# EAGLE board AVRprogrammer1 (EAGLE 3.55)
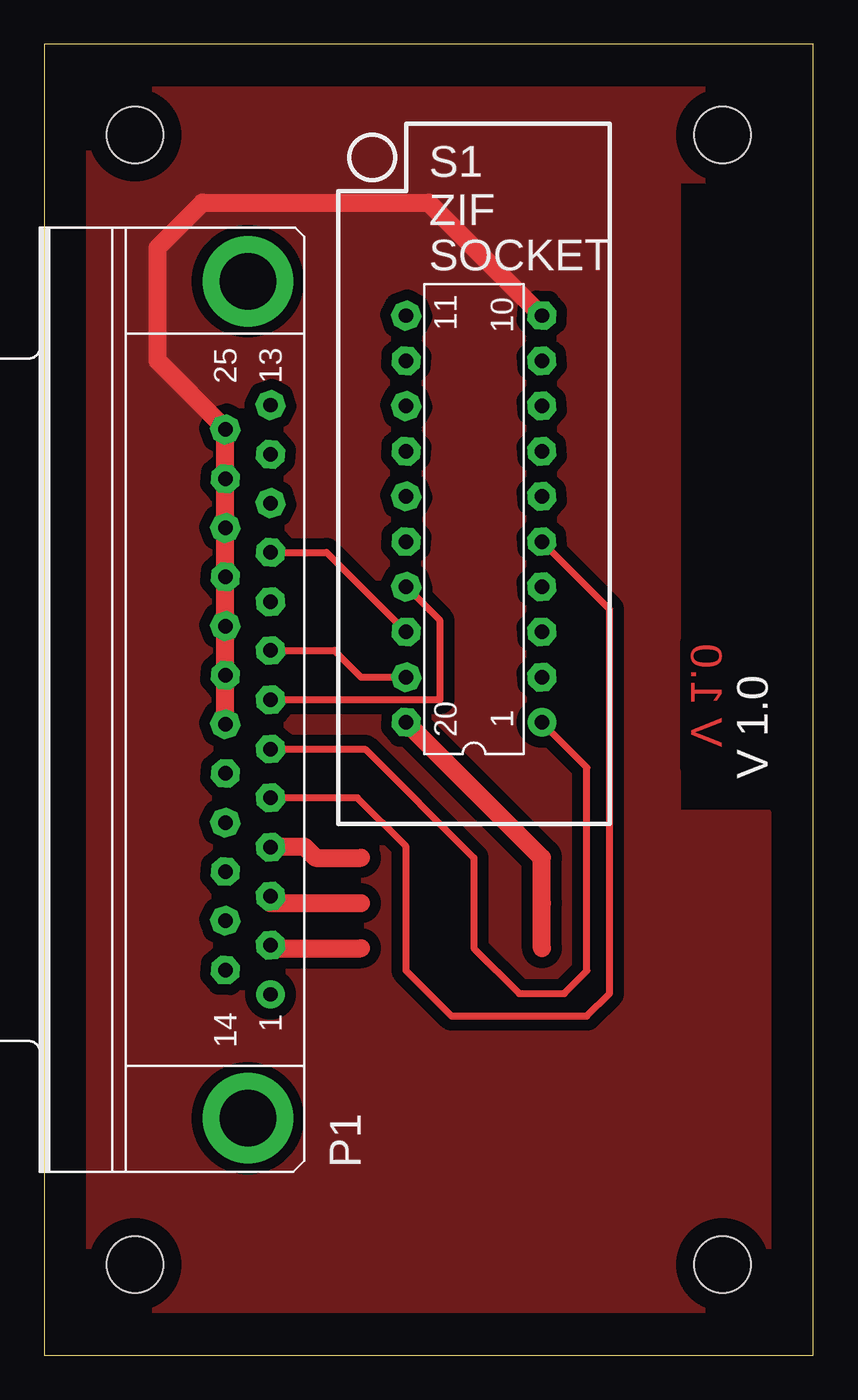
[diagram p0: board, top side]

Size 43.18 x 73.66 mm. Coordinates in mm from the lower left corner, seen from the top.
Outline: 0,0 43.18,0 43.18,73.66 0,73.66 0,0
Copper layers used: Top
Holes 3.17 mm at 5.08,68.58 5.08,5.08 38.1,5.08 38.1,68.58

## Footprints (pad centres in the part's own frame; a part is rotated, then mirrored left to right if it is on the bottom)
5H = drill 0.813 pad 1.6 round:  -16.561,-1.27 | drill 0.813 pad 1.6 octagon:  -13.792,-1.27;  -11.049,-1.27;  -8.28,-1.27;  -5.512,-1.27;  -2.769,-1.27;  0,-1.27;  2.769,-1.27;  5.512,-1.27;  8.28,-1.27;  11.049,-1.27;  13.792,-1.27;  16.561,-1.27;  -15.189,1.27;  -12.421,1.27;  -9.652,1.27;  -6.909,1.27;  -4.14,1.27;  -1.372,1.27;  1.372,1.27;  4.14,1.27;  6.909,1.27;  9.652,1.27;  12.421,1.27;  15.189,1.27 | drill 3.175 pad 5.08 round:  -23.52,0;  23.52,0
L20 = drill 0.813 pad 1.6 round:  -11.43,-3.81 | drill 0.813 pad 1.6 octagon:  -8.89,-3.81;  -6.35,-3.81;  -3.81,-3.81;  -1.27,-3.81;  1.27,-3.81;  3.81,-3.81;  6.35,-3.81;  8.89,-3.81;  11.43,-3.81;  11.43,3.81;  8.89,3.81;  6.35,3.81;  3.81,3.81;  1.27,3.81;  -1.27,3.81;  -3.81,3.81;  -6.35,3.81;  -8.89,3.81;  -11.43,3.81

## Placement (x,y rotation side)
P1  DB25 Female  [5H]  11.43,36.83 90 top
R1  220  [07/10]  22.86,22.86 180 top
R2  220  [07/10]  22.86,25.4 180 top
R3  220  [07/10]  22.86,27.94 180 top
S1  90S2313-10  [L20]  24.13,46.99 90 top

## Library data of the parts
P1 = D-sub
R1-R3 = R
S1 = AT90SMCU

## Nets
B0: P1. R1.
B1: P1. R2.
B2: P1. R3.
CLK: P1. S1.
GND: P1. S1.
MISO: P1. S1.
MOSI: P1. S1.
RESET: P1. S1.
SCK: P1. S1.
VCC: R1. R2. R3. S1.

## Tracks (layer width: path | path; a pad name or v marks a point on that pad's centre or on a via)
B0
  Top 1.016: 12.7,23.04 12.7,22.86 17.78,22.86
B1
  Top 1.016: 12.7,25.78 12.7,25.4 17.78,25.4
B2
  Top 1.016: 17.78,27.94 15.24,27.94 14.61,28.58 12.7,28.58 12.7,28.55
CLK
  Top 0.406: 12.7,31.32 17.58,31.32 20.32,28.58 20.32,21.59 22.86,19.05 30.48,19.05 31.75,20.32 31.75,41.91 27.94,45.72
GND
  Top 1.016: 10.16,35.46 10.16,38.2 10.16,40.97 10.16,43.74 | 10.16,43.74 10.16,43.82 | 10.16,43.74 10.16,46.48 10.16,49.25 10.16,52.02 10.16,52.07 6.35,55.88 6.35,62.23 8.89,64.77 21.59,64.77 27.94,58.42
  pour Top (isolate 0.61): 2.54,71.12 40.64,71.12 40.64,66.04 35.56,66.04 35.56,30.48 40.64,30.48 40.64,2.54 2.54,2.54
MISO
  Top 0.406: 12.7,45.11 15.85,45.11 20.32,40.64
MOSI
  Top 0.406: 12.7,36.83 22.23,36.83 22.23,41.28 20.32,43.18
RESET
  Top 0.406: 12.7,34.06 18.01,34.06 24.13,27.94 24.13,22.86 26.67,20.32 29.21,20.32 30.48,21.59 30.48,33.02 27.94,35.56
SCK
  Top 0.406: 12.7,39.6 16.28,39.6 17.78,38.1 20.32,38.1
VCC
  Top 1.016: 27.94,22.86 27.94,25.4 27.94,27.94 S1.

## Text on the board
Top: V 1.0
tPlace: ZIF | SOCKET | V 1.0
